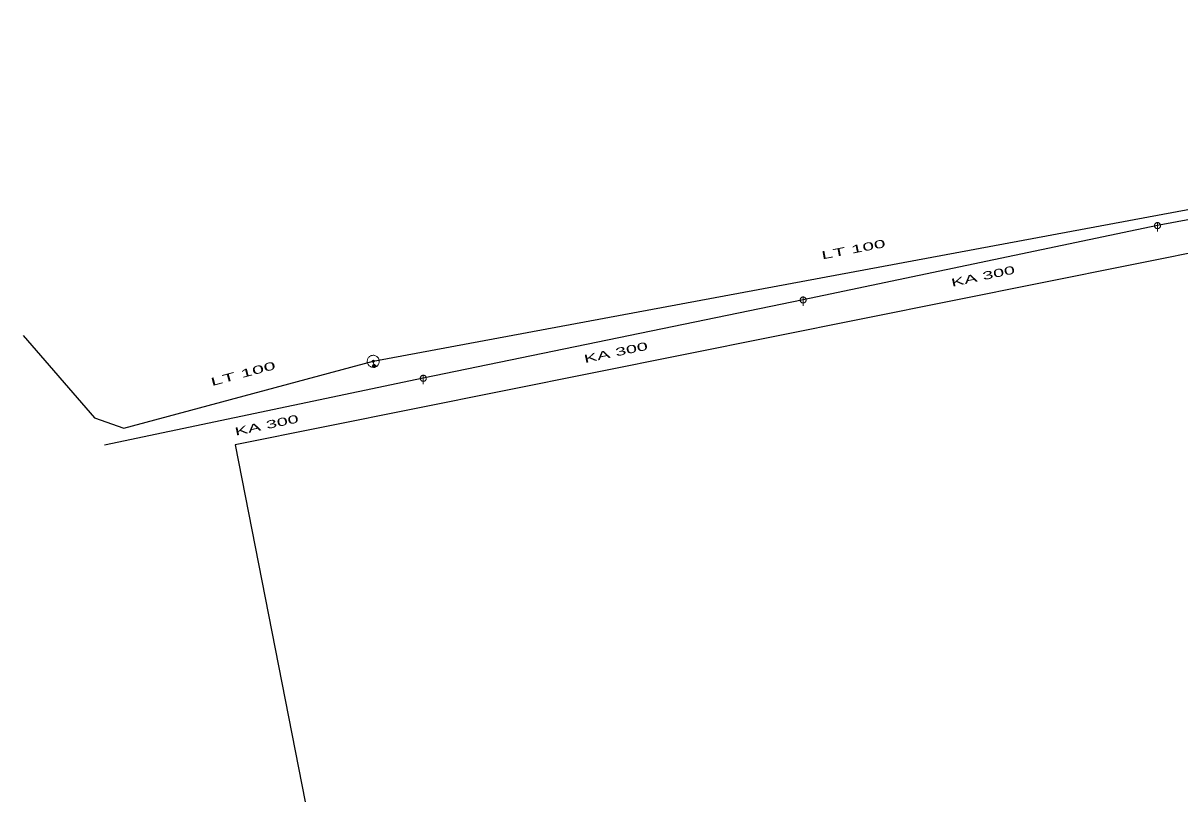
# Model space of a CAD drawing. Extents: x -687515 to -686506, y -974029 to -973461.
# Drawn here: x -687485.8 to -687389.5, y -973678.4 to -973614.2 of the extents above; entities that cross this region are included whole.
import ezdxf
from ezdxf.enums import TextEntityAlignment as Align

# ---------------------------------------------------------------- set-up
doc = ezdxf.new("R2010")
doc.units = 0
doc.header["$LTSCALE"] = 0.27
for name, color, linetype, lineweight in [('1', 7, 'Continuous', 13), ('14', 7, 'Continuous', 25), ('17', 7, 'Continuous', 25), ('22', 7, 'Continuous', 13), ('47', 7, 'Continuous', 13), ('9', 7, 'Continuous', 13)]:
    doc.layers.add(name, color=color, linetype=linetype, lineweight=lineweight)

msp = doc.modelspace()

# ---------------------------------------------------------------- linework, layer by layer
at = {"layer": '14'}
for p, q in [((-687376.437, -973628.208), (-687391.359, -973631.065)), ((-687391.359, -973631.065), (-687420.873, -973637.26)), ((-687420.873, -973637.26), (-687452.508, -973643.78)), ((-687452.508, -973643.78), (-687479.058, -973649.352))]:
    msp.add_line(p, q, dxfattribs=at)
at = {"layer": '14', "lineweight": 13}
msp.add_line((-687456.605, -973642.761), (-687456.678, -973642.368), dxfattribs=at)
at = {"layer": '17'}
msp.add_line((-687456.678, -973642.368), (-687375.989, -973627.339), dxfattribs=at)
for points in [[(-686645.309, -973464.46), (-686646.34, -973464.75), (-686680.188, -973471.317), (-686771.188, -973470.317), (-686761.188, -973557.317), (-686894.188, -973571.317), (-686953.188, -973578.317), (-686955.188, -973554.317), (-687116.188, -973577.317), (-687229.188, -973601.317), (-687468.188, -973649.317), (-687458.188, -973700.317)], [(-687485.839, -973640.219), (-687479.897, -973647.07), (-687477.44, -973647.949), (-687456.678, -973642.368)]]:
    msp.add_lwpolyline(points, dxfattribs=at)
at = {"layer": '22'}
for p, q in [((-687391.358, -973630.813), (-687391.359, -973631.556)), ((-687420.872, -973637.008), (-687420.873, -973637.752)), ((-687452.507, -973643.528), (-687452.508, -973644.272))]:
    msp.add_line(p, q, dxfattribs=at)
for points in [[(-687391.107, -973631.065), (-687391.108, -973631.039), (-687391.112, -973631.013), (-687391.118, -973630.987), (-687391.128, -973630.963), (-687391.14, -973630.939), (-687391.154, -973630.917), (-687391.171, -973630.896), (-687391.189, -973630.878), (-687391.21, -973630.861), (-687391.232, -973630.847), (-687391.256, -973630.835), (-687391.28, -973630.825), (-687391.306, -973630.819), (-687391.332, -973630.815), (-687391.358, -973630.813), (-687391.384, -973630.814), (-687391.41, -973630.818), (-687391.436, -973630.824), (-687391.461, -973630.834), (-687391.484, -973630.846), (-687391.506, -973630.86), (-687391.527, -973630.877), (-687391.545, -973630.895), (-687391.562, -973630.916), (-687391.576, -973630.938), (-687391.588, -973630.962), (-687391.598, -973630.986), (-687391.605, -973631.012), (-687391.609, -973631.038), (-687391.611, -973631.064), (-687391.61, -973631.09), (-687391.606, -973631.116), (-687391.599, -973631.142), (-687391.589, -973631.167), (-687391.577, -973631.19), (-687391.563, -973631.212), (-687391.546, -973631.233), (-687391.528, -973631.251), (-687391.507, -973631.268), (-687391.485, -973631.282), (-687391.462, -973631.294), (-687391.437, -973631.304), (-687391.411, -973631.311), (-687391.385, -973631.315), (-687391.359, -973631.316), (-687391.333, -973631.316), (-687391.307, -973631.312), (-687391.281, -973631.305), (-687391.257, -973631.295), (-687391.233, -973631.283), (-687391.211, -973631.269), (-687391.19, -973631.252), (-687391.172, -973631.234), (-687391.155, -973631.213), (-687391.141, -973631.191), (-687391.129, -973631.168), (-687391.119, -973631.143), (-687391.113, -973631.117), (-687391.109, -973631.091)], [(-687420.621, -973637.26), (-687420.622, -973637.234), (-687420.626, -973637.208), (-687420.632, -973637.182), (-687420.642, -973637.158), (-687420.654, -973637.134), (-687420.668, -973637.112), (-687420.685, -973637.091), (-687420.703, -973637.073), (-687420.724, -973637.056), (-687420.746, -973637.042), (-687420.77, -973637.03), (-687420.794, -973637.02), (-687420.82, -973637.014), (-687420.846, -973637.01), (-687420.872, -973637.008), (-687420.898, -973637.009), (-687420.924, -973637.013), (-687420.95, -973637.019), (-687420.975, -973637.029), (-687420.998, -973637.041), (-687421.02, -973637.055), (-687421.041, -973637.072), (-687421.059, -973637.09), (-687421.076, -973637.111), (-687421.09, -973637.133), (-687421.102, -973637.157), (-687421.112, -973637.181), (-687421.119, -973637.207), (-687421.123, -973637.233), (-687421.125, -973637.259), (-687421.124, -973637.285), (-687421.12, -973637.311), (-687421.113, -973637.337), (-687421.103, -973637.362), (-687421.091, -973637.385), (-687421.077, -973637.407), (-687421.06, -973637.428), (-687421.042, -973637.446), (-687421.021, -973637.463), (-687420.999, -973637.477), (-687420.976, -973637.489), (-687420.951, -973637.499), (-687420.925, -973637.506), (-687420.899, -973637.51), (-687420.873, -973637.512), (-687420.847, -973637.511), (-687420.821, -973637.507), (-687420.795, -973637.5), (-687420.771, -973637.49), (-687420.747, -973637.478), (-687420.725, -973637.464), (-687420.704, -973637.447), (-687420.686, -973637.429), (-687420.669, -973637.408), (-687420.655, -973637.386), (-687420.643, -973637.363), (-687420.633, -973637.338), (-687420.627, -973637.312), (-687420.623, -973637.286)], [(-687452.256, -973643.78), (-687452.257, -973643.754), (-687452.261, -973643.728), (-687452.267, -973643.702), (-687452.277, -973643.678), (-687452.289, -973643.654), (-687452.303, -973643.632), (-687452.32, -973643.611), (-687452.338, -973643.593), (-687452.359, -973643.576), (-687452.381, -973643.562), (-687452.405, -973643.55), (-687452.429, -973643.54), (-687452.455, -973643.534), (-687452.481, -973643.53), (-687452.507, -973643.528), (-687452.533, -973643.529), (-687452.559, -973643.533), (-687452.585, -973643.539), (-687452.61, -973643.549), (-687452.633, -973643.561), (-687452.655, -973643.575), (-687452.676, -973643.592), (-687452.694, -973643.61), (-687452.711, -973643.631), (-687452.725, -973643.653), (-687452.737, -973643.677), (-687452.747, -973643.701), (-687452.754, -973643.727), (-687452.758, -973643.753), (-687452.76, -973643.779), (-687452.759, -973643.805), (-687452.755, -973643.831), (-687452.748, -973643.857), (-687452.738, -973643.882), (-687452.726, -973643.905), (-687452.712, -973643.927), (-687452.695, -973643.948), (-687452.677, -973643.966), (-687452.656, -973643.983), (-687452.634, -973643.997), (-687452.611, -973644.009), (-687452.586, -973644.019), (-687452.56, -973644.026), (-687452.534, -973644.03), (-687452.508, -973644.032), (-687452.482, -973644.031), (-687452.456, -973644.027), (-687452.43, -973644.02), (-687452.406, -973644.01), (-687452.382, -973643.998), (-687452.36, -973643.984), (-687452.339, -973643.967), (-687452.321, -973643.949), (-687452.304, -973643.928), (-687452.29, -973643.906), (-687452.278, -973643.883), (-687452.268, -973643.858), (-687452.262, -973643.832), (-687452.258, -973643.806)]]:
    msp.add_lwpolyline(points, close=True, dxfattribs=at)
at = {"layer": '47'}
for points in [[(-687456.19, -973642.255), (-687456.205, -973642.205), (-687456.225, -973642.156), (-687456.249, -973642.11), (-687456.278, -973642.067), (-687456.312, -973642.026), (-687456.35, -973641.99), (-687456.391, -973641.958), (-687456.436, -973641.931), (-687456.482, -973641.908), (-687456.532, -973641.889), (-687456.583, -973641.876), (-687456.635, -973641.87), (-687456.686, -973641.868), (-687456.739, -973641.872), (-687456.79, -973641.88), (-687456.84, -973641.895), (-687456.889, -973641.915), (-687456.936, -973641.94), (-687456.978, -973641.968), (-687457.019, -973642.002), (-687457.055, -973642.04), (-687457.088, -973642.082), (-687457.115, -973642.126), (-687457.138, -973642.172), (-687457.156, -973642.222), (-687457.169, -973642.273), (-687457.176, -973642.325), (-687457.177, -973642.376), (-687457.173, -973642.429), (-687457.165, -973642.48), (-687457.15, -973642.53), (-687457.13, -973642.579), (-687457.106, -973642.626), (-687457.077, -973642.668), (-687457.043, -973642.709), (-687457.006, -973642.745), (-687456.964, -973642.778), (-687456.92, -973642.805), (-687456.873, -973642.828), (-687456.823, -973642.846), (-687456.772, -973642.859), (-687456.721, -973642.866), (-687456.669, -973642.867), (-687456.616, -973642.863), (-687456.565, -973642.855), (-687456.515, -973642.84), (-687456.466, -973642.82), (-687456.42, -973642.796), (-687456.377, -973642.767), (-687456.336, -973642.733), (-687456.3, -973642.696), (-687456.268, -973642.655), (-687456.24, -973642.61), (-687456.218, -973642.563), (-687456.199, -973642.513), (-687456.186, -973642.462), (-687456.18, -973642.411), (-687456.178, -973642.359), (-687456.182, -973642.306)], [(-687456.598, -973642.349), (-687456.6, -973642.34), (-687456.603, -973642.333), (-687456.607, -973642.326), (-687456.612, -973642.318), (-687456.618, -973642.312), (-687456.624, -973642.306), (-687456.63, -973642.3), (-687456.638, -973642.296), (-687456.646, -973642.292), (-687456.654, -973642.289), (-687456.662, -973642.287), (-687456.671, -973642.286), (-687456.679, -973642.286), (-687456.687, -973642.286), (-687456.696, -973642.288), (-687456.705, -973642.29), (-687456.712, -973642.293), (-687456.719, -973642.297), (-687456.727, -973642.302), (-687456.733, -973642.308), (-687456.739, -973642.314), (-687456.745, -973642.32), (-687456.749, -973642.328), (-687456.754, -973642.336), (-687456.756, -973642.344), (-687456.758, -973642.352), (-687456.759, -973642.361), (-687456.759, -973642.369), (-687456.759, -973642.377), (-687456.757, -973642.386), (-687456.755, -973642.395), (-687456.752, -973642.402), (-687456.748, -973642.409), (-687456.743, -973642.417), (-687456.737, -973642.423), (-687456.732, -973642.429), (-687456.725, -973642.435), (-687456.717, -973642.439), (-687456.709, -973642.444), (-687456.701, -973642.446), (-687456.693, -973642.448), (-687456.684, -973642.449), (-687456.676, -973642.449), (-687456.668, -973642.449), (-687456.659, -973642.447), (-687456.65, -973642.445), (-687456.643, -973642.442), (-687456.636, -973642.438), (-687456.628, -973642.433), (-687456.622, -973642.427), (-687456.616, -973642.422), (-687456.61, -973642.415), (-687456.606, -973642.407), (-687456.602, -973642.399), (-687456.599, -973642.391), (-687456.597, -973642.383), (-687456.596, -973642.374), (-687456.596, -973642.366), (-687456.596, -973642.358)]]:
    msp.add_lwpolyline(points, close=True, dxfattribs=at)
at = {"layer": '9'}
msp.add_line((-687456.478, -973642.761), (-687456.353, -973642.761), dxfattribs=at)
for points in [[(-687456.605, -973642.887), (-687456.592, -973642.886), (-687456.579, -973642.884), (-687456.566, -973642.881), (-687456.554, -973642.876), (-687456.542, -973642.87), (-687456.531, -973642.863), (-687456.521, -973642.855), (-687456.511, -973642.845), (-687456.503, -973642.835), (-687456.496, -973642.824), (-687456.49, -973642.812), (-687456.485, -973642.8), (-687456.482, -973642.787), (-687456.48, -973642.774), (-687456.478, -973642.761), (-687456.479, -973642.748), (-687456.481, -973642.735), (-687456.484, -973642.722), (-687456.489, -973642.71), (-687456.495, -973642.698), (-687456.502, -973642.687), (-687456.51, -973642.677), (-687456.52, -973642.667), (-687456.53, -973642.659), (-687456.541, -973642.652), (-687456.553, -973642.646), (-687456.565, -973642.641), (-687456.578, -973642.638), (-687456.591, -973642.636), (-687456.604, -973642.635), (-687456.617, -973642.635), (-687456.63, -973642.637), (-687456.643, -973642.64), (-687456.655, -973642.645), (-687456.667, -973642.651), (-687456.678, -973642.658), (-687456.688, -973642.666), (-687456.698, -973642.676), (-687456.706, -973642.686), (-687456.713, -973642.697), (-687456.719, -973642.709), (-687456.724, -973642.721), (-687456.727, -973642.734), (-687456.729, -973642.747), (-687456.731, -973642.76), (-687456.73, -973642.773), (-687456.728, -973642.786), (-687456.725, -973642.799), (-687456.72, -973642.811), (-687456.714, -973642.823), (-687456.707, -973642.834), (-687456.699, -973642.844), (-687456.689, -973642.854), (-687456.679, -973642.862), (-687456.668, -973642.869), (-687456.656, -973642.875), (-687456.644, -973642.88), (-687456.631, -973642.883), (-687456.618, -973642.885)], [(-687456.605, -973642.867), (-687456.594, -973642.867), (-687456.583, -973642.865), (-687456.572, -973642.862), (-687456.562, -973642.858), (-687456.552, -973642.853), (-687456.543, -973642.847), (-687456.534, -973642.84), (-687456.526, -973642.832), (-687456.519, -973642.823), (-687456.513, -973642.814), (-687456.508, -973642.804), (-687456.504, -973642.794), (-687456.501, -973642.783), (-687456.499, -973642.772), (-687456.499, -973642.761), (-687456.498, -973642.75), (-687456.5, -973642.739), (-687456.503, -973642.728), (-687456.507, -973642.718), (-687456.512, -973642.708), (-687456.518, -973642.699), (-687456.525, -973642.69), (-687456.533, -973642.682), (-687456.542, -973642.675), (-687456.551, -973642.669), (-687456.561, -973642.664), (-687456.571, -973642.66), (-687456.582, -973642.657), (-687456.593, -973642.655), (-687456.604, -973642.655), (-687456.615, -973642.654), (-687456.626, -973642.656), (-687456.637, -973642.659), (-687456.647, -973642.663), (-687456.657, -973642.668), (-687456.666, -973642.674), (-687456.675, -973642.681), (-687456.683, -973642.689), (-687456.69, -973642.698), (-687456.696, -973642.707), (-687456.701, -973642.717), (-687456.705, -973642.727), (-687456.708, -973642.738), (-687456.71, -973642.749), (-687456.711, -973642.76), (-687456.711, -973642.771), (-687456.709, -973642.782), (-687456.706, -973642.793), (-687456.702, -973642.803), (-687456.697, -973642.813), (-687456.691, -973642.822), (-687456.684, -973642.831), (-687456.676, -973642.839), (-687456.667, -973642.846), (-687456.658, -973642.852), (-687456.648, -973642.857), (-687456.638, -973642.861), (-687456.627, -973642.864), (-687456.616, -973642.866)], [(-687456.605, -973642.848), (-687456.596, -973642.847), (-687456.587, -973642.846), (-687456.578, -973642.843), (-687456.57, -973642.84), (-687456.562, -973642.836), (-687456.554, -973642.831), (-687456.547, -973642.825), (-687456.541, -973642.819), (-687456.535, -973642.812), (-687456.53, -973642.804), (-687456.526, -973642.796), (-687456.523, -973642.788), (-687456.52, -973642.779), (-687456.519, -973642.77), (-687456.517, -973642.761), (-687456.518, -973642.752), (-687456.519, -973642.743), (-687456.522, -973642.734), (-687456.525, -973642.726), (-687456.529, -973642.718), (-687456.534, -973642.71), (-687456.54, -973642.703), (-687456.546, -973642.697), (-687456.553, -973642.691), (-687456.561, -973642.686), (-687456.569, -973642.682), (-687456.577, -973642.679), (-687456.586, -973642.676), (-687456.595, -973642.675), (-687456.604, -973642.674), (-687456.613, -973642.674), (-687456.622, -973642.675), (-687456.631, -973642.678), (-687456.639, -973642.681), (-687456.647, -973642.685), (-687456.655, -973642.69), (-687456.662, -973642.696), (-687456.668, -973642.702), (-687456.674, -973642.709), (-687456.679, -973642.717), (-687456.683, -973642.725), (-687456.686, -973642.733), (-687456.689, -973642.742), (-687456.69, -973642.751), (-687456.692, -973642.76), (-687456.691, -973642.769), (-687456.69, -973642.778), (-687456.687, -973642.787), (-687456.684, -973642.795), (-687456.68, -973642.803), (-687456.675, -973642.811), (-687456.669, -973642.818), (-687456.663, -973642.824), (-687456.656, -973642.83), (-687456.648, -973642.835), (-687456.64, -973642.839), (-687456.632, -973642.842), (-687456.623, -973642.845), (-687456.614, -973642.846)], [(-687456.605, -973642.828), (-687456.598, -973642.828), (-687456.591, -973642.826), (-687456.584, -973642.825), (-687456.578, -973642.822), (-687456.572, -973642.819), (-687456.566, -973642.815), (-687456.56, -973642.811), (-687456.555, -973642.806), (-687456.551, -973642.8), (-687456.547, -973642.794), (-687456.544, -973642.788), (-687456.541, -973642.782), (-687456.54, -973642.775), (-687456.538, -973642.768), (-687456.538, -973642.761), (-687456.537, -973642.754), (-687456.539, -973642.747), (-687456.54, -973642.74), (-687456.543, -973642.734), (-687456.546, -973642.727), (-687456.55, -973642.722), (-687456.554, -973642.716), (-687456.559, -973642.711), (-687456.565, -973642.707), (-687456.571, -973642.703), (-687456.577, -973642.7), (-687456.583, -973642.697), (-687456.59, -973642.695), (-687456.597, -973642.694), (-687456.604, -973642.694), (-687456.611, -973642.693), (-687456.618, -973642.694), (-687456.625, -973642.696), (-687456.631, -973642.699), (-687456.638, -973642.702), (-687456.643, -973642.706), (-687456.649, -973642.71), (-687456.654, -973642.715), (-687456.658, -973642.721), (-687456.662, -973642.726), (-687456.665, -973642.733), (-687456.668, -973642.739), (-687456.67, -973642.746), (-687456.671, -973642.753), (-687456.672, -973642.76), (-687456.672, -973642.767), (-687456.671, -973642.774), (-687456.669, -973642.781), (-687456.666, -973642.787), (-687456.663, -973642.793), (-687456.659, -973642.799), (-687456.655, -973642.805), (-687456.65, -973642.81), (-687456.644, -973642.814), (-687456.639, -973642.818), (-687456.632, -973642.821), (-687456.626, -973642.824), (-687456.619, -973642.825), (-687456.612, -973642.827)], [(-687456.605, -973642.808), (-687456.6, -973642.808), (-687456.595, -973642.807), (-687456.59, -973642.806), (-687456.586, -973642.804), (-687456.581, -973642.802), (-687456.577, -973642.799), (-687456.574, -973642.796), (-687456.57, -973642.792), (-687456.567, -973642.789), (-687456.564, -973642.785), (-687456.562, -973642.78), (-687456.56, -973642.776), (-687456.559, -973642.771), (-687456.558, -973642.766), (-687456.558, -973642.761), (-687456.557, -973642.756), (-687456.558, -973642.751), (-687456.559, -973642.746), (-687456.561, -973642.742), (-687456.563, -973642.737), (-687456.566, -973642.733), (-687456.569, -973642.729), (-687456.573, -973642.726), (-687456.576, -973642.723), (-687456.58, -973642.72), (-687456.585, -973642.718), (-687456.589, -973642.716), (-687456.594, -973642.715), (-687456.599, -973642.714), (-687456.604, -973642.714), (-687456.609, -973642.713), (-687456.614, -973642.714), (-687456.619, -973642.715), (-687456.623, -973642.717), (-687456.628, -973642.719), (-687456.632, -973642.722), (-687456.636, -973642.725), (-687456.639, -973642.728), (-687456.642, -973642.732), (-687456.645, -973642.736), (-687456.647, -973642.741), (-687456.649, -973642.745), (-687456.65, -973642.75), (-687456.651, -973642.755), (-687456.652, -973642.76), (-687456.652, -973642.765), (-687456.651, -973642.77), (-687456.65, -973642.775), (-687456.648, -973642.779), (-687456.646, -973642.784), (-687456.643, -973642.788), (-687456.64, -973642.791), (-687456.637, -973642.795), (-687456.633, -973642.798), (-687456.629, -973642.801), (-687456.624, -973642.803), (-687456.62, -973642.805), (-687456.615, -973642.806), (-687456.61, -973642.807)], [(-687456.605, -973642.788), (-687456.602, -973642.788), (-687456.599, -973642.788), (-687456.597, -973642.787), (-687456.594, -973642.786), (-687456.591, -973642.785), (-687456.589, -973642.783), (-687456.587, -973642.781), (-687456.585, -973642.779), (-687456.583, -973642.777), (-687456.581, -973642.775), (-687456.58, -973642.772), (-687456.579, -973642.769), (-687456.578, -973642.767), (-687456.578, -973642.764), (-687456.578, -973642.761), (-687456.577, -973642.758), (-687456.577, -973642.755), (-687456.578, -973642.752), (-687456.579, -973642.75), (-687456.58, -973642.747), (-687456.582, -973642.745), (-687456.584, -973642.742), (-687456.586, -973642.74), (-687456.588, -973642.739), (-687456.59, -973642.737), (-687456.593, -973642.736), (-687456.596, -973642.735), (-687456.598, -973642.734), (-687456.601, -973642.734), (-687456.604, -973642.733), (-687456.607, -973642.733), (-687456.61, -973642.733), (-687456.613, -973642.734), (-687456.615, -973642.735), (-687456.618, -973642.736), (-687456.62, -973642.738), (-687456.623, -973642.739), (-687456.625, -973642.741), (-687456.626, -973642.744), (-687456.628, -973642.746), (-687456.629, -973642.749), (-687456.63, -973642.751), (-687456.631, -973642.754), (-687456.631, -973642.757), (-687456.633, -973642.76), (-687456.632, -973642.763), (-687456.632, -973642.766), (-687456.631, -973642.768), (-687456.63, -973642.771), (-687456.629, -973642.774), (-687456.627, -973642.776), (-687456.626, -973642.778), (-687456.624, -973642.78), (-687456.621, -973642.782), (-687456.619, -973642.784), (-687456.616, -973642.785), (-687456.614, -973642.786), (-687456.611, -973642.787), (-687456.608, -973642.788)], [(-687456.605, -973642.769), (-687456.604, -973642.769), (-687456.603, -973642.769), (-687456.603, -973642.768), (-687456.602, -973642.768), (-687456.601, -973642.768), (-687456.6, -973642.767), (-687456.6, -973642.767), (-687456.599, -973642.766), (-687456.599, -973642.766), (-687456.598, -973642.765), (-687456.598, -973642.764), (-687456.598, -973642.763), (-687456.597, -973642.763), (-687456.597, -973642.762), (-687456.597, -973642.761), (-687456.597, -973642.76), (-687456.597, -973642.759), (-687456.597, -973642.759), (-687456.597, -973642.758), (-687456.597, -973642.757), (-687456.598, -973642.756), (-687456.598, -973642.756), (-687456.599, -973642.755), (-687456.599, -973642.755), (-687456.6, -973642.754), (-687456.601, -973642.754), (-687456.602, -973642.753), (-687456.602, -973642.753), (-687456.603, -973642.753), (-687456.604, -973642.753), (-687456.605, -973642.753), (-687456.606, -973642.753), (-687456.606, -973642.753), (-687456.607, -973642.754), (-687456.608, -973642.753), (-687456.609, -973642.754), (-687456.609, -973642.754), (-687456.61, -973642.755), (-687456.61, -973642.755), (-687456.611, -973642.756), (-687456.611, -973642.757), (-687456.612, -973642.758), (-687456.612, -973642.758), (-687456.612, -973642.759), (-687456.613, -973642.76), (-687456.613, -973642.761), (-687456.613, -973642.762), (-687456.613, -973642.762), (-687456.612, -973642.763), (-687456.612, -973642.764), (-687456.611, -973642.765), (-687456.611, -973642.765), (-687456.61, -973642.766), (-687456.61, -973642.766), (-687456.609, -973642.767), (-687456.608, -973642.767), (-687456.607, -973642.767), (-687456.607, -973642.769), (-687456.606, -973642.769)]]:
    msp.add_lwpolyline(points, close=True, dxfattribs=at)
msp.add_lwpolyline([(-687456.387, -973642.73), (-687456.353, -973642.761), (-687456.388, -973642.792)], dxfattribs=at)

# ---------------------------------------------------------------- texts
at = {"layer": '1'}
for s, rotation, width, p in [('LT 100', 11, 1.95, (-687416.622, -973633.367)), ('KA 300', 12, 1.85, (-687405.821, -973635.604)), ('KA 300', 12, 1.85, (-687436.403, -973641.953)), ('LT 100', 15, 2, (-687467.436, -973643.717)), ('KA 300', 12, 1.85, (-687465.488, -973648.007))]:
    msp.add_text(s, height=0.6667, rotation=rotation, dxfattribs=dict(at, width=width)).set_placement(p, align=Align.CENTER)

doc.saveas('drawing.dxf')
